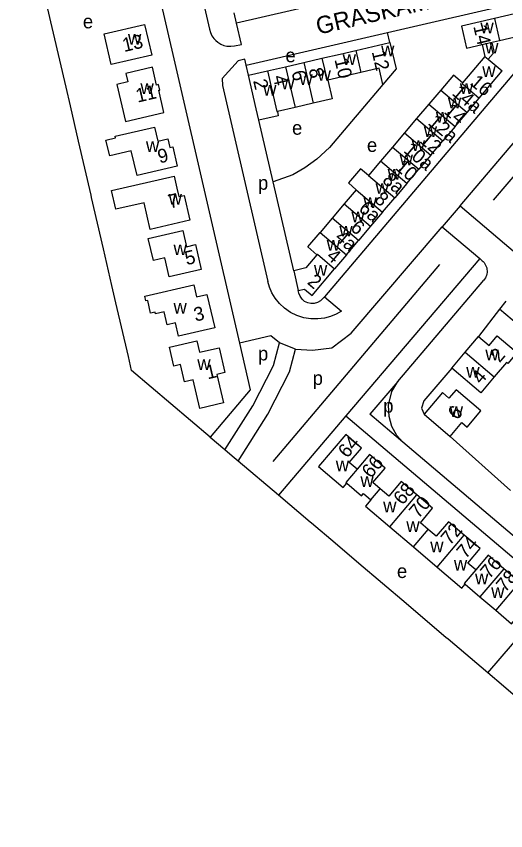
# Model space of a CAD drawing. Extents: x 155696 to 157795, y 382328 to 384028.
# Drawn here: x 156696.3 to 156838, y 382337.3 to 382573 of the extents above; entities that cross this region are included whole.
import ezdxf

# ---------------------------------------------------------------- set-up
doc = ezdxf.new("R2010")
doc.units = 0
for name, color, linetype in [('BLT_Basislijn', 7, 'Continuous'), ('BLT_Bebouwing', 7, 'Continuous'), ('BLT_Centroide', 7, 'Continuous'), ('BLT_Gemeentegrens', 7, 'Continuous'), ('BLT_Huisnummer', 7, 'Continuous'), ('BLT_Huisnummer_ tussenligend', 7, 'Continuous'), ('BLT_Onderverdeling_panden', 7, 'Continuous'), ('BLT_Straatnaam', 7, 'Continuous'), ('BLT_Vlakafsluiter', 7, 'Continuous')]:
    doc.layers.add(name, color=color, linetype=linetype)

msp = doc.modelspace()

# ---------------------------------------------------------------- linework, layer by layer
at = {"layer": 'BLT_Basislijn'}
for p, q in [((156834.46, 382519.74), (156886.08, 382580.75)), ((156803.8, 382568.29), (156844.99, 382577.8)), ((156856.41, 382575.46), (156785.51, 382491.83)), ((156762.86, 382558.83), (156803.8, 382568.29)), ((156804.48, 382565.37), (156803.8, 382568.29)), ((156770.66, 382525.08), (156766.54, 382542.91)), ((156776.61, 382499.38), (156770.66, 382525.08)), ((156770.7, 382444.21), (156818.91, 382501.19)), ((156838.01, 382490.58), (156836.21, 382488.23)), ((156836.21, 382488.23), (156830.13, 382480.33)), ((156875.7, 382454.77), (156836.21, 382488.23)), ((156777.17, 382476.65), (156772.48, 382478.47)), ((156806.71, 382467.36), (156798.65, 382457.85)), ((156808.2, 382449.76), (156798.65, 382457.85)), ((156791.68, 382457.36), (156772.23, 382434.4)), ((156821.86, 382451.43), (156839.32, 382435.82)), ((156832.83, 382382.98), (156852.34, 382405.98))]:
    msp.add_line(p, q, dxfattribs=at)
for points in [[(156727.73, 382622.05), (156742.5, 382558.12)], [(156740.38, 382620.62), (156752.25, 382569.21), (156752.53, 382568.29), (156752.96, 382567.32), (156753.48, 382566.56), (156754.04, 382565.97), (156754.67, 382565.46), (156755.49, 382564.94), (156756.42, 382564.57), (156757.3, 382564.38), (156758.4, 382564.29), (156759.51, 382564.46), (156761.47, 382564.86), (156760.05, 382571.01)], [(156830.61, 382587.31), (156760.05, 382571.01)], [(156760.05, 382571.01), (156759.37, 382573.94)], [(156762.86, 382558.83), (156762.45, 382560.6), (156760.52, 382560.1), (156755.91, 382554.96), (156756.01, 382552.93), (156769.11, 382496.24)], [(156742.5, 382558.12), (156760.91, 382478.4)], [(156763.54, 382555.91), (156762.86, 382558.83)], [(156802.43, 382553.27), (156786.94, 382534.99), (156783.34, 382531.63), (156779.84, 382529.09), (156776.37, 382527.14), (156770.66, 382525.08)], [(156824.76, 382518.18), (156843.9, 382540.6)], [(156824.76, 382518.18), (156851.73, 382495.32)], [(156777.17, 382476.65), (156782.04, 382476.38), (156787.62, 382477.05), (156793.27, 382481.28), (156819.57, 382512.09)], [(156819.57, 382512.09), (156830.44, 382502.88)], [(156830.44, 382502.88), (156791.68, 382457.36)], [(156830.44, 382502.88), (156831.17, 382502.26)], [(156831.17, 382502.26), (156831.46, 382502), (156831.72, 382501.7), (156831.96, 382501.36), (156832.17, 382501), (156832.34, 382500.6), (156832.47, 382500.18), (156832.55, 382499.75), (156832.59, 382499.31), (156832.57, 382498.87), (156832.51, 382498.44), (156832.41, 382498.02), (156832.26, 382497.62), (156832.08, 382497.26), (156831.87, 382496.92), (156831.63, 382496.61)], [(156785.51, 382491.83), (156790.41, 382487.68), (156788.94, 382486.84), (156787.29, 382486.15), (156785.48, 382485.66), (156783.55, 382485.42), (156781.54, 382485.45), (156779.51, 382485.78), (156777.52, 382486.41), (156775.66, 382487.32), (156773.96, 382488.49), (156772.49, 382489.87), (156771.27, 382491.38), (156770.3, 382492.99), (156769.59, 382494.62), (156769.11, 382496.24)], [(156806.71, 382467.36), (156831.63, 382496.61)], [(156785.51, 382491.83), (156784.39, 382490.65), (156783.52, 382490.15), (156782.56, 382489.88), (156781.58, 382489.86), (156780.66, 382490.07), (156779.78, 382490.5), (156779.02, 382491.15), (156778.44, 382491.97), (156778.1, 382492.86), (156777.93, 382493.61)], [(156772.48, 382478.47), (156769.95, 382480.49), (156760.91, 382478.4)], [(156756.7, 382447.58), (156764.83, 382460.32), (156770.73, 382471.91), (156772.48, 382478.47)], [(156760.55, 382444.31), (156769.17, 382457.84), (156775.43, 382470.11), (156777.17, 382476.65)], [(156760.91, 382478.4), (156764.04, 382464.88)], [(156822.38, 382471.18), (156814.31, 382461.7), (156813.6, 382459.63), (156814.33, 382457.82)], [(156808.2, 382449.76), (156806.5, 382451.69), (156805.06, 382454.27), (156804.22, 382457.2), (156804.06, 382460.47), (156805, 382464.45), (156806.71, 382467.36)], [(156764.04, 382464.88), (156752.43, 382451.19)], [(156791.68, 382457.36), (156852.34, 382405.98)], [(156889.25, 382381.11), (156808.2, 382449.76)]]:
    msp.add_lwpolyline(points, dxfattribs=at)
at = {"layer": 'BLT_Bebouwing'}
for p, q in [((156794.55, 382563.08), (156801.15, 382564.6)), ((156801.15, 382564.6), (156804.48, 382565.37)), ((156804.48, 382565.37), (156806.23, 382557.75)), ((156831.14, 382564.85), (156831.96, 382561.32)), ((156784.79, 382560.82), (156790.05, 382562.03)), ((156790.05, 382562.03), (156794.55, 382563.08)), ((156774.26, 382558.39), (156779.52, 382559.6)), ((156779.52, 382559.6), (156784.79, 382560.82)), ((156831.96, 382561.32), (156825.51, 382553.73)), ((156832.91, 382560.57), (156836.93, 382557.17)), ((156763.54, 382555.91), (156769, 382557.17)), ((156769, 382557.17), (156774.26, 382558.39)), ((156796.01, 382556.75), (156786.45, 382554.54)), ((156830.29, 382549.29), (156836.93, 382557.17)), ((156765.79, 382546.17), (156763.54, 382555.91)), ((156822.83, 382555.99), (156819.17, 382551.64)), ((156825.51, 382553.73), (156822.83, 382555.99)), ((156819.17, 382551.64), (156815.68, 382547.52)), ((156815.68, 382547.52), (156812.19, 382543.4)), ((156826.8, 382545.17), (156830.29, 382549.29)), ((156823.31, 382541.05), (156826.8, 382545.17)), ((156812.19, 382543.4), (156808.7, 382539.28)), ((156823.31, 382541.05), (156819.82, 382536.94)), ((156808.7, 382539.28), (156805.21, 382535.16)), ((156816.33, 382532.82), (156819.82, 382536.94)), ((156805.21, 382535.16), (156801.71, 382531.04)), ((156801.71, 382531.04), (156798.22, 382526.93)), ((156816.33, 382532.82), (156812.83, 382528.7)), ((156809.34, 382524.58), (156812.83, 382528.7)), ((156809.34, 382524.58), (156805.85, 382520.46)), ((156794.73, 382522.81), (156791.24, 382518.69)), ((156802.36, 382516.34), (156805.85, 382520.46)), ((156791.24, 382518.69), (156787.75, 382514.57)), ((156787.75, 382514.57), (156784.25, 382510.45)), ((156802.36, 382516.34), (156798.87, 382512.22)), ((156798.87, 382512.22), (156795.37, 382508.1)), ((156791.88, 382503.98), (156795.37, 382508.1)), ((156783.34, 382503.98), (156780.16, 382500.21)), ((156791.88, 382503.98), (156788.45, 382499.95)), ((156780.16, 382500.21), (156776.61, 382499.38)), ((156776.61, 382499.38), (156777.93, 382493.61)), ((156781.91, 382492.22), (156788.45, 382499.95)), ((156804.44, 382425.26), (156811.29, 382419.44)), ((156811.29, 382419.44), (156818.16, 382413.61)), ((156842.01, 382409.29), (156837.44, 382413.16)), ((156826.2, 382408.64), (156830.52, 382404.99)), ((156830.52, 382404.99), (156835.09, 382401.11))]:
    msp.add_line(p, q, dxfattribs=at)
for points in [[(156846.49, 382568.4), (156845.03, 382574.73), (156834.68, 382572.34)], [(156834.68, 382572.34), (156825.13, 382570.14), (156826.59, 382563.8), (156831.14, 382564.85)], [(156836.14, 382566.01), (156841.99, 382567.36), (156842.76, 382564)], [(156832.91, 382560.57), (156834.33, 382562.24), (156833.59, 382565.43)], [(156833.59, 382565.43), (156836.14, 382566.01)], [(156739.04, 382545.12), (156737.55, 382551.57), (156737.84, 382551.64), (156737.48, 382553.22), (156736.93, 382553.09), (156735.75, 382558.22), (156728.01, 382556.43), (156728.57, 382553.99), (156725.45, 382553.27), (156727.93, 382542.55), (156739.04, 382545.12)], [(156802.43, 382553.27), (156801.35, 382557.98), (156796.01, 382556.75)], [(156806.23, 382557.75), (156802.43, 382553.27)], [(156786.45, 382554.54), (156787.72, 382549.08), (156782.25, 382547.81)], [(156782.25, 382547.81), (156777, 382546.6)], [(156766.54, 382542.91), (156765.79, 382546.17)], [(156771.88, 382545.42), (156772.16, 382544.21), (156766.54, 382542.91)], [(156777, 382546.6), (156771.88, 382545.42)], [(156798.22, 382526.93), (156795.92, 382528.87), (156792.43, 382524.75), (156794.73, 382522.81)], [(156783.34, 382503.98), (156780.66, 382506.23), (156784.25, 382510.45)], [(156739.17, 382487.46), (156736.65, 382486.88), (156736.53, 382487.4), (156735.2, 382487.1), (156734.35, 382490.76), (156733.86, 382490.65), (156733.53, 382492.03), (156747.7, 382495.3), (156748.51, 382491.79), (156751.51, 382492.49), (156753.74, 382482.81), (156743.32, 382480.41), (156742.43, 382484.25), (156740.04, 382483.7), (156739.17, 382487.46)], [(156777.93, 382493.61), (156779.77, 382494.04), (156781.91, 382492.22)], [(156826.26, 382475.76), (156830.13, 382480.33)], [(156830.13, 382480.33), (156833.18, 382477.74), (156835.54, 382480.52), (156840.46, 382476.39), (156840.3, 382476.2), (156841.14, 382475.5), (156838.62, 382472.53), (156838.24, 382472.85), (156834.66, 382468.63)], [(156822.38, 382471.18), (156826.26, 382475.76)], [(156834.66, 382468.63), (156830.77, 382464.05), (156822.38, 382471.18)], [(156821.86, 382451.43), (156825.28, 382455.44), (156826.8, 382454.15), (156830.77, 382458.81), (156823.6, 382464.9), (156821.52, 382462.54), (156819.67, 382464.14), (156814.33, 382457.82)], [(156814.33, 382457.82), (156821.86, 382451.43)], [(156795, 382441.95), (156792.69, 382443.88), (156796.24, 382448.07), (156791.69, 382451.97), (156783.8, 382442.77), (156790.91, 382436.67), (156791.96, 382437.9)], [(156801.65, 382436.29), (156799.55, 382438.06), (156803.11, 382442.26), (156798.55, 382446.15), (156795, 382441.95)], [(156791.96, 382437.9), (156796.24, 382434.23), (156796.85, 382434.94), (156798.97, 382433.12)], [(156812.27, 382434.5), (156807.7, 382438.39), (156804.14, 382434.18), (156801.65, 382436.29)], [(156815.55, 382424.47), (156813.27, 382426.41), (156816.83, 382430.62), (156812.27, 382434.5)], [(156798.97, 382433.12), (156797.37, 382431.26), (156804.44, 382425.26)], [(156825.99, 382422.86), (156821.41, 382426.74), (156817.83, 382422.52), (156815.55, 382424.47)], [(156829.28, 382412.84), (156826.99, 382414.79), (156830.58, 382418.99), (156825.99, 382422.86)], [(156837.44, 382413.16), (156832.86, 382417.03), (156829.28, 382412.84)], [(156818.16, 382413.61), (156825.28, 382407.57), (156826.2, 382408.64)], [(156835.09, 382401.11), (156839.67, 382397.24), (156846.59, 382405.42), (156842.01, 382409.29)]]:
    msp.add_lwpolyline(points, dxfattribs=at)
for points in [[(156721.77, 382567.87), (156733.47, 382570.57), (156735.51, 382561.7), (156723.82, 382559)], [(156724.9, 382538.26), (156736.37, 382540.93), (156737.31, 382536.85), (156740.2, 382537.51), (156740.78, 382535.06), (156741.62, 382535.25), (156742.93, 382529.58), (156731.28, 382526.91), (156729.62, 382534.07), (156723.37, 382532.6), (156722.28, 382537.13), (156725.02, 382537.78)], [(156723.92, 382522.56), (156742.01, 382526.77), (156742.83, 382523.24), (156743.4, 382520.8), (156744.9, 382521.16), (156746.55, 382513.96), (156735.1, 382511.31), (156733.32, 382519.03), (156725.16, 382517.14)], [(156734.52, 382508.69), (156744.51, 382511), (156745.58, 382506.31), (156748.16, 382506.92), (156749.81, 382499.76), (156740.6, 382497.63), (156739.33, 382503.12), (156735.99, 382502.35)], [(156740.69, 382477.25), (156748.61, 382479.08), (156749.38, 382475.76), (156755.06, 382477.07), (156756.72, 382469.9), (156754.36, 382469.35), (156756.27, 382461.1), (156749.42, 382459.52), (156747.51, 382467.77), (156745.05, 382467.2), (156743.88, 382472.24), (156741.95, 382471.79)]]:
    msp.add_lwpolyline(points, close=True, dxfattribs=at)
at = {"layer": 'BLT_Gemeentegrens'}
msp.add_line((156772.23, 382434.4), (156760.55, 382444.31), dxfattribs=at)
for points in [[(156752.43, 382451.19), (156729.69, 382470.5), (156728.76, 382474.53), (156725.16, 382490.06), (156724, 382495.11), (156721.56, 382505.66), (156718.12, 382520.52), (156717.97, 382521.18), (156714.34, 382536.88), (156711.99, 382547.04), (156710.75, 382552.43), (156707.12, 382568.11), (156706.36, 382571.41), (156703.54, 382583.6), (156699.93, 382599.18), (156696.32, 382614.8)], [(156756.7, 382447.58), (156752.48, 382451.15), (156752.43, 382451.19)], [(156758.84, 382445.76), (156756.7, 382447.58)], [(156760.55, 382444.31), (156758.84, 382445.76)], [(156832.83, 382382.98), (156821.27, 382392.79), (156820.68, 382393.29), (156816.05, 382397.22), (156809.19, 382403.04), (156802.33, 382408.86), (156795.46, 382414.68), (156788.6, 382420.51), (156781.74, 382426.33), (156781.4, 382426.61), (156772.23, 382434.4)], [(156886.61, 382337.35), (156880.86, 382342.22), (156842.87, 382374.46), (156837.32, 382379.17), (156832.83, 382382.98)]]:
    msp.add_lwpolyline(points, dxfattribs=at)
at = {"layer": 'BLT_Onderverdeling_panden'}
for p, q in [((156834.68, 382572.34), (156836.14, 382566.01)), ((156831.14, 382564.85), (156833.59, 382565.43)), ((156794.55, 382563.08), (156796.01, 382556.75)), ((156779.52, 382559.6), (156782.25, 382547.81)), ((156831.96, 382561.32), (156832.91, 382560.57)), ((156774.26, 382558.39), (156777, 382546.6)), ((156819.17, 382551.64), (156826.8, 382545.17)), ((156815.68, 382547.52), (156823.31, 382541.05)), ((156812.19, 382543.4), (156819.82, 382536.94)), ((156808.7, 382539.28), (156816.33, 382532.82)), ((156805.21, 382535.16), (156812.83, 382528.7)), ((156809.34, 382524.58), (156801.71, 382531.04)), ((156798.22, 382526.93), (156805.85, 382520.46)), ((156794.73, 382522.81), (156802.36, 382516.34)), ((156791.24, 382518.69), (156798.87, 382512.22)), ((156795.37, 382508.1), (156787.75, 382514.57)), ((156784.25, 382510.45), (156791.88, 382503.98)), ((156826.26, 382475.76), (156834.66, 382468.63)), ((156798.97, 382433.12), (156801.65, 382436.29)), ((156804.44, 382425.26), (156812.27, 382434.5)), ((156811.29, 382419.44), (156815.55, 382424.47)), ((156818.16, 382413.61), (156825.99, 382422.86)), ((156837.44, 382413.16), (156830.52, 382404.99)), ((156842.01, 382409.29), (156835.09, 382401.11))]:
    msp.add_line(p, q, dxfattribs=at)
for points in [[(156784.79, 382560.82), (156786.27, 382554.5), (156786.45, 382554.54)], [(156769, 382557.17), (156771.74, 382545.39), (156771.88, 382545.42)], [(156825.51, 382553.73), (156825.39, 382553.58), (156830.29, 382549.29)], [(156783.34, 382503.98), (156783.49, 382504.15), (156788.45, 382499.95)], [(156795, 382441.95), (156791.73, 382438.09), (156791.96, 382437.9)], [(156829.28, 382412.84), (156825.93, 382408.87), (156826.2, 382408.64)]]:
    msp.add_lwpolyline(points, dxfattribs=at)
at = {"layer": 'BLT_Vlakafsluiter'}
msp.add_line((156824.76, 382518.18), (156819.57, 382512.09), dxfattribs=at)

# ---------------------------------------------------------------- texts
at = {"layer": 'BLT_Centroide'}
for s, p in [('e', (156715.6, 382569.49)), ('w', (156830.64, 382568.06)), ('w', (156728.64, 382564.78)), ('w', (156801.89, 382561.44)), ('w', (156832.03, 382562.22)), ('e', (156774.22, 382559.68)), ('w', (156790.78, 382558.88)), ('w', (156783.52, 382554.31)), ('w', (156831.19, 382555.38)), ('w', (156773, 382551.89)), ('w', (156778.25, 382553.09)), ('w', (156732.25, 382550.48)), ('w', (156767.77, 382550.03)), ('w', (156824.69, 382550.53)), ('w', (156821.24, 382546.34)), ('w', (156817.75, 382542.22)), ('e', (156776.13, 382538.71)), ('w', (156814.26, 382538.09)), ('w', (156733.84, 382533.75)), ('e', (156797.81, 382533.74)), ('w', (156810.77, 382534)), ('w', (156807.27, 382529.88)), ('w', (156803.78, 382525.75)), ('p', (156766.28, 382522.8)), ('w', (156800.29, 382521.62)), ('w', (156740.41, 382518.5)), ('w', (156796.8, 382517.5)), ('w', (156793.3, 382513.41)), ('w', (156789.81, 382509.28)), ('w', (156786.16, 382505.16)), ('w', (156741.82, 382503.88)), ('w', (156782.47, 382497.91)), ('w', (156741.82, 382486.96)), ('p', (156766.28, 382473.41)), ('w', (156832.08, 382473.44)), ('w', (156748.7, 382470.64)), ('w', (156826.55, 382468.41)), ('p', (156782.1, 382466.32)), ('p', (156802.52, 382458.31)), ('w', (156821.75, 382457.02)), ('w', (156788.78, 382441.36)), ('w', (156795.91, 382436.83)), ('w', (156802.5, 382429.45)), ('w', (156809.21, 382423.77)), ('w', (156816.12, 382417.92)), ('w', (156822.97, 382412.63)), ('e', (156806.49, 382410.46)), ('w', (156829.09, 382408.65)), ('w', (156833.76, 382404.69))]:
    msp.add_text(s, height=4, dxfattribs=at).set_placement(p)
at = {"layer": 'BLT_Huisnummer'}
for s, rotation, p in [('14', 283.0092, (156828.57, 382570.07)), ('13', 13.0061, (156727.52, 382562.62)), ('12', 283.0092, (156799.18, 382562.71)), ('6', 283.0092, (156775.96, 382556.88)), ('2', 283.0092, (156764.86, 382554.32)), ('16', 319.712, (156827.38, 382553.42)), ('11', 13.0077, (156731.41, 382547.98)), ('14a', 319.712, (156822.17, 382550.44)), ('14', 319.712, (156819.84, 382545.14)), ('12a', 319.712, (156815.22, 382541.88)), ('12', 319.712, (156812.77, 382536.71)), ('10a', 319.712, (156808.16, 382533.86)), ('9', 14.1107, (156737.79, 382530.37)), ('10', 319.712, (156805.78, 382528.88)), ('8a', 319.712, (156802, 382525.13)), ('7', 13.0061, (156740.77, 382517.32)), ('8', 319.712, (156799.7, 382519.59)), ('6a', 319.712, (156795.16, 382516.9)), ('6', 319.712, (156792.76, 382511.37)), ('4a', 319.712, (156788.31, 382508.55)), ('5', 13.0064, (156745.59, 382500.94)), ('4', 319.712, (156785.85, 382503.12)), ('2', 319.712, (156780.31, 382495.76)), ('3', 13.0061, (156748.17, 382484.63)), ('2', 49.6852, (156836.19, 382472.57)), ('1', 13.0077, (156751.7, 382467.93)), ('4', 49.6852, (156830.85, 382466.29)), ('6', 49.6852, (156823.88, 382455.96)), ('64', 49.6852, (156792.1, 382444.93)), ('68', 49.6852, (156808.12, 382431.35)), ('72', 49.6852, (156821.85, 382419.72)), ('76', 49.6852, (156833.27, 382409.99))]:
    msp.add_text(s, height=4, rotation=rotation, dxfattribs=at).set_placement(p)
at = {"layer": 'BLT_Huisnummer_ tussenligend'}
for s, rotation, p in [('10', 283.0092, (156788.39, 382560.47)), ('8', 283.0092, (156780.91, 382557.62)), ('4', 283.0092, (156770.56, 382555.53)), ('66', 49.6852, (156798.96, 382439.11)), ('70', 49.6852, (156812.69, 382427.47)), ('74', 49.6852, (156826.41, 382415.82)), ('78', 49.6852, (156837.85, 382406.12))]:
    msp.add_text(s, height=4, rotation=rotation, dxfattribs=at).set_placement(p)
at = {"layer": 'BLT_Straatnaam'}
msp.add_text('GRASKAMP', height=5, rotation=13.007, dxfattribs=at).set_placement((156783.71, 382567.63))

doc.saveas('drawing.dxf')
